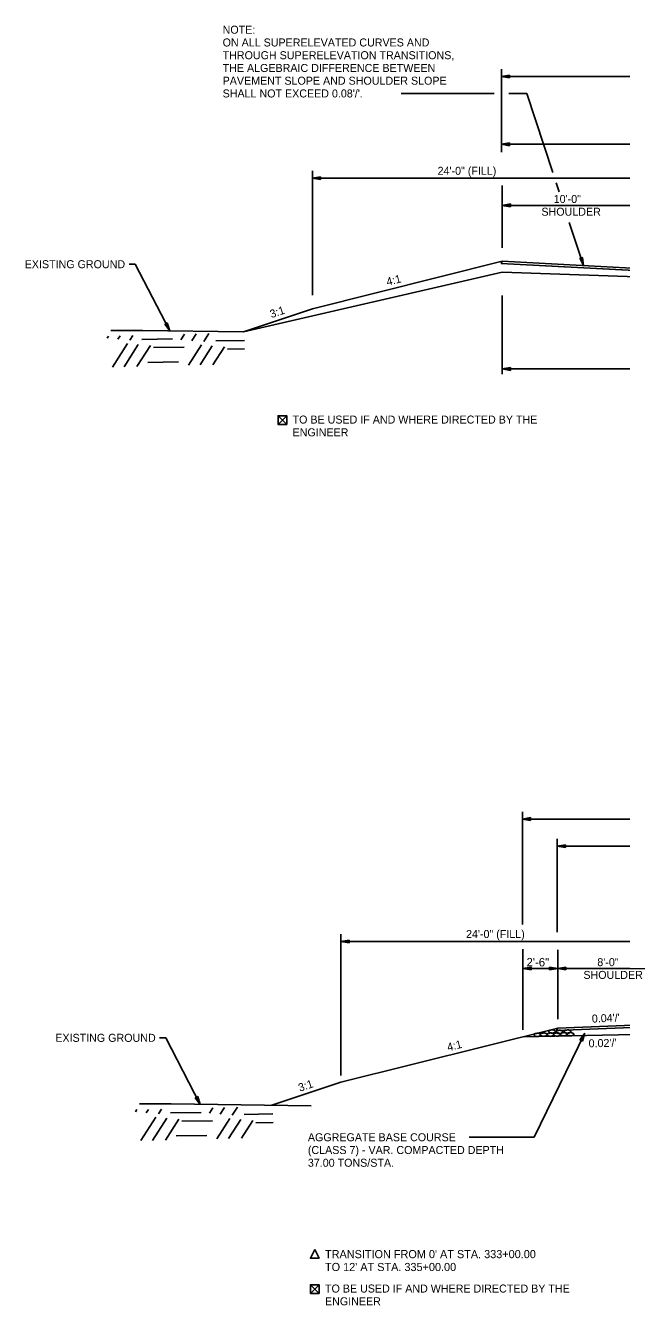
# Model space of a CAD drawing. Extents: x 1398183 to 1398373, y 1967240 to 1968889.
# Drawn here: x 1398185.9 to 1398229.8, y 1968484.8 to 1968579.2 of the extents above; entities that cross this region are included whole.
import ezdxf

# ---------------------------------------------------------------- set-up
doc = ezdxf.new("R2010")
doc.units = 0
for name, color, linetype in [('1', 7, 'Continuous'), ('10', 7, 'Continuous'), ('19', 7, 'Continuous'), ('42', 7, 'Continuous'), ('9', 7, 'Continuous')]:
    doc.layers.add(name, color=color, linetype=linetype)

# ---------------------------------------------------------------- blocks, each defined once
blk = doc.blocks.new('ROCKS')
at = {"layer": '1'}
blk.add_spline([(0.013, 0.06), (0.053, 0.053), (0.107, 0.033), (0.133, 0.013), (0.133, -0.007), (0.12, -0.033), (0.107, -0.04), (0.073, -0.053), (0.033, -0.067), (0.013, -0.067), (-0.02, -0.06), (-0.06, -0.053), (-0.087, -0.047), (-0.113, -0.02), (-0.113, -0.007), (-0.107, 0.02), (-0.087, 0.033), (-0.067, 0.047), (-0.033, 0.053), (-0.02, 0.06), (0.013, 0.06)], degree=3, dxfattribs=at)

msp = doc.modelspace()

# ---------------------------------------------------------------- linework, layer by layer
at = {"layer": '10'}
for p, q in [((1398204.509, 1968550.426), (1398205.15, 1968549.785)), ((1398205.15, 1968550.426), (1398204.509, 1968549.785)), ((1398204.89, 1968549.785), (1398204.901, 1968549.785)), ((1398206.903, 1968486.339), (1398207.544, 1968485.698)), ((1398207.544, 1968486.339), (1398206.903, 1968485.698)), ((1398207.284, 1968485.698), (1398207.296, 1968485.698))]:
    msp.add_line(p, q, dxfattribs=at)
for points in [[(1398204.901, 1968549.785), (1398205.15, 1968549.785), (1398205.15, 1968550.426), (1398204.509, 1968550.426), (1398204.509, 1968549.785), (1398204.89, 1968549.785)], [(1398207.296, 1968485.698), (1398207.544, 1968485.698), (1398207.544, 1968486.339), (1398206.903, 1968486.339), (1398206.903, 1968485.698), (1398207.284, 1968485.698)]]:
    msp.add_lwpolyline(points, dxfattribs=at)
msp.add_lwpolyline([(1398207.214, 1968488.933), (1398206.893, 1968488.292), (1398207.535, 1968488.292)], close=True, dxfattribs=at)
at = {"layer": '19'}
for p, q in [((1398220.994, 1968569.859), (1398220.994, 1968575.999)), ((1398221.594, 1968575.551), (1398220.994, 1968575.446)), ((1398272.994, 1968575.446), (1398220.994, 1968575.446)), ((1398220.994, 1968575.446), (1398221.594, 1968575.341)), ((1398221.594, 1968575.496), (1398221.154, 1968575.461)), ((1398221.154, 1968575.431), (1398221.594, 1968575.391)), ((1398221.594, 1968575.341), (1398221.594, 1968575.551)), ((1398220.466, 1968574.187), (1398213.602, 1968574.185)), ((1398222.858, 1968574.187), (1398221.532, 1968574.187)), ((1398222.858, 1968574.187), (1398224.78, 1968568.377)), ((1398221.594, 1968570.55), (1398220.994, 1968570.446)), ((1398220.994, 1968570.446), (1398282.96, 1968570.446)), ((1398220.994, 1968570.446), (1398221.594, 1968570.34)), ((1398221.594, 1968570.495), (1398221.154, 1968570.461)), ((1398221.154, 1968570.431), (1398221.594, 1968570.39)), ((1398221.594, 1968570.34), (1398221.594, 1968570.55)), ((1398207.052, 1968559.324), (1398207.052, 1968568.492)), ((1398207.652, 1968568.051), (1398207.052, 1968567.946)), ((1398231.052, 1968567.946), (1398207.052, 1968567.946)), ((1398207.052, 1968567.946), (1398207.652, 1968567.841)), ((1398207.652, 1968567.996), (1398207.212, 1968567.961)), ((1398207.212, 1968567.931), (1398207.652, 1968567.891)), ((1398207.652, 1968567.841), (1398207.652, 1968568.051)), ((1398221.052, 1968562.824), (1398221.052, 1968567.406)), ((1398225.032, 1968567.613), (1398225.251, 1968566.951)), ((1398221.652, 1968566.05), (1398221.052, 1968565.946)), ((1398221.052, 1968565.946), (1398221.652, 1968565.84)), ((1398221.052, 1968565.946), (1398231.052, 1968565.946)), ((1398221.652, 1968565.995), (1398221.212, 1968565.961)), ((1398221.652, 1968565.84), (1398221.652, 1968566.05)), ((1398221.212, 1968565.931), (1398221.652, 1968565.89)), ((1398226, 1968564.687), (1398227.052, 1968561.506)), ((1398221.052, 1968561.824), (1398207.052, 1968558.324)), ((1398221.052, 1968561.824), (1398220.967, 1968561.654)), ((1398226.972, 1968562.11), (1398226.773, 1968562.046)), ((1398226.773, 1968562.046), (1398227.052, 1968561.506)), ((1398226.818, 1968562.057), (1398226.989, 1968561.655)), ((1398227.014, 1968561.66), (1398226.922, 1968562.089)), ((1398227.052, 1968561.506), (1398226.972, 1968562.11)), ((1398221.052, 1968553.49), (1398221.052, 1968559.294)), ((1398207.052, 1968558.324), (1398201.951, 1968556.624)), ((1398196.144, 1968557.182), (1398196.33, 1968557.277)), ((1398196.514, 1968556.698), (1398196.144, 1968557.182)), ((1398196.431, 1968556.834), (1398196.194, 1968557.202)), ((1398196.29, 1968557.253), (1398196.453, 1968556.847)), ((1398196.33, 1968557.277), (1398196.514, 1968556.698)), ((1398221.652, 1968553.985), (1398221.052, 1968553.88)), ((1398221.052, 1968553.88), (1398221.652, 1968553.775)), ((1398221.052, 1968553.88), (1398255.052, 1968553.88)), ((1398221.652, 1968553.93), (1398221.212, 1968553.895)), ((1398221.212, 1968553.865), (1398221.652, 1968553.825)), ((1398221.652, 1968553.775), (1398221.652, 1968553.985)), ((1398222.545, 1968512.904), (1398222.545, 1968521.226)), ((1398223.145, 1968520.79), (1398222.545, 1968520.685)), ((1398222.545, 1968520.685), (1398279.917, 1968520.685)), ((1398222.545, 1968520.685), (1398223.145, 1968520.58)), ((1398223.145, 1968520.735), (1398222.705, 1968520.7)), ((1398222.705, 1968520.67), (1398223.145, 1968520.63)), ((1398223.145, 1968520.58), (1398223.145, 1968520.79)), ((1398225.119, 1968512.351), (1398225.119, 1968519.233)), ((1398225.719, 1968518.79), (1398225.119, 1968518.685)), ((1398225.719, 1968518.58), (1398225.719, 1968518.79)), ((1398275.152, 1968518.685), (1398225.119, 1968518.685)), ((1398225.119, 1968518.685), (1398225.719, 1968518.58)), ((1398225.719, 1968518.735), (1398225.279, 1968518.7)), ((1398225.279, 1968518.67), (1398225.719, 1968518.63)), ((1398209.15, 1968501.772), (1398209.15, 1968512.207)), ((1398209.75, 1968511.765), (1398209.15, 1968511.66)), ((1398233.15, 1968511.66), (1398209.15, 1968511.66)), ((1398209.15, 1968511.66), (1398209.75, 1968511.555)), ((1398209.75, 1968511.71), (1398209.31, 1968511.675)), ((1398209.31, 1968511.645), (1398209.75, 1968511.605)), ((1398209.75, 1968511.555), (1398209.75, 1968511.765)), ((1398222.578, 1968505.129), (1398222.578, 1968511.101)), ((1398225.15, 1968505.932), (1398225.15, 1968511.041)), ((1398223.178, 1968509.765), (1398222.578, 1968509.66)), ((1398222.578, 1968509.66), (1398225.15, 1968509.66)), ((1398222.578, 1968509.66), (1398223.178, 1968509.555)), ((1398223.178, 1968509.71), (1398222.738, 1968509.675)), ((1398222.738, 1968509.645), (1398223.178, 1968509.605)), ((1398223.178, 1968509.555), (1398223.178, 1968509.765)), ((1398224.55, 1968509.765), (1398224.55, 1968509.555)), ((1398225.15, 1968509.66), (1398224.55, 1968509.765)), ((1398224.99, 1968509.675), (1398224.55, 1968509.71)), ((1398224.55, 1968509.555), (1398225.15, 1968509.66)), ((1398224.55, 1968509.605), (1398224.99, 1968509.645)), ((1398225.75, 1968509.765), (1398225.15, 1968509.66)), ((1398225.15, 1968509.66), (1398225.75, 1968509.555)), ((1398225.15, 1968509.66), (1398233.15, 1968509.66)), ((1398225.75, 1968509.71), (1398225.31, 1968509.675)), ((1398225.31, 1968509.645), (1398225.75, 1968509.605)), ((1398225.75, 1968509.555), (1398225.75, 1968509.765)), ((1398225.15, 1968505.272), (1398209.15, 1968501.272)), ((1398223.415, 1968497.225), (1398227.143, 1968504.883)), ((1398225.15, 1968505.272), (1398225.065, 1968505.102)), ((1398227.143, 1968504.883), (1398226.779, 1968504.395)), ((1398227.061, 1968504.747), (1398226.828, 1968504.374)), ((1398226.922, 1968504.325), (1398227.086, 1968504.734)), ((1398226.966, 1968504.302), (1398227.143, 1968504.883)), ((1398226.779, 1968504.395), (1398226.966, 1968504.302)), ((1398209.15, 1968501.272), (1398204.049, 1968499.572)), ((1398198.401, 1968500.128), (1398198.587, 1968500.224)), ((1398198.771, 1968499.644), (1398198.401, 1968500.128)), ((1398198.689, 1968499.78), (1398198.451, 1968500.148)), ((1398198.548, 1968500.199), (1398198.71, 1968499.793)), ((1398198.587, 1968500.224), (1398198.771, 1968499.644)), ((1398218.617, 1968497.225), (1398223.415, 1968497.225))]:
    msp.add_line(p, q, dxfattribs=at)
for points in [[(1398193.514, 1968561.604), (1398193.96, 1968561.604), (1398196.514, 1968556.698)], [(1398220.967, 1968561.654), (1398243.052, 1968560.491), (1398267.137, 1968559.216), (1398273.137, 1968558.898)], [(1398221.052, 1968561.824), (1398231.052, 1968561.294), (1398243.052, 1968560.658), (1398255.052, 1968560.022), (1398267.052, 1968559.386), (1398273.052, 1968559.068)], [(1398225.065, 1968505.102), (1398233.065, 1968505.422), (1398245.15, 1968505.666), (1398269.237, 1968505.182), (1398275.235, 1968504.942)], [(1398245.15, 1968505.832), (1398233.15, 1968505.592), (1398225.15, 1968505.272)], [(1398233.15, 1968504.841), (1398222.578, 1968504.629)], [(1398195.772, 1968504.55), (1398196.218, 1968504.55), (1398198.771, 1968499.644)]]:
    msp.add_lwpolyline(points, dxfattribs=at)
for points in [[(1398220.967, 1968561.654), (1398230.818, 1968561.138), (1398243.052, 1968560.491), (1398267.137, 1968559.216), (1398273.137, 1968558.898), (1398273.052, 1968559.068), (1398267.052, 1968559.386), (1398243.052, 1968560.658), (1398231.052, 1968561.294), (1398221.052, 1968561.824)], [(1398225.065, 1968505.102), (1398233.065, 1968505.422), (1398245.15, 1968505.666), (1398269.252, 1968505.191), (1398275.237, 1968504.942), (1398275.15, 1968505.112), (1398269.152, 1968505.352), (1398245.15, 1968505.832), (1398233.15, 1968505.592), (1398225.15, 1968505.272)]]:
    msp.add_lwpolyline(points, close=True, dxfattribs=at)
at = {"layer": '42'}
msp.add_line((1398221.052, 1968561.011), (1398201.951, 1968556.624), dxfattribs=at)
for points in [[(1398221.052, 1968561.011), (1398243.052, 1968560.263), (1398255.052, 1968559.855)], [(1398192.182, 1968556.725), (1398194.519, 1968556.725), (1398201.951, 1968556.624)], [(1398194.28, 1968499.673), (1398196.617, 1968499.673), (1398206.951, 1968499.533)]]:
    msp.add_lwpolyline(points, dxfattribs=at)
at = {"layer": '9'}
for p, q in [((1398191.889, 1968556.15), (1398191.99, 1968556.306)), ((1398192.286, 1968554.019), (1398193.401, 1968555.759)), ((1398192.689, 1968556.076), (1398192.849, 1968556.327)), ((1398193.145, 1968554.039), (1398194.2, 1968555.686)), ((1398193.581, 1968556.005), (1398193.801, 1968556.35)), ((1398194.098, 1968554.062), (1398195.092, 1968555.614)), ((1398194.469, 1968556.063), (1398196.731, 1968556.099)), ((1398197.344, 1968556.039), (1398197.601, 1968556.44)), ((1398197.898, 1968554.152), (1398198.856, 1968555.648)), ((1398198.144, 1968555.965), (1398198.461, 1968556.461)), ((1398198.757, 1968554.173), (1398199.655, 1968555.574)), ((1398199.036, 1968555.894), (1398199.413, 1968556.483)), ((1398199.924, 1968555.952), (1398202.03, 1968555.985)), ((1398195.318, 1968555.453), (1398197.58, 1968555.488)), ((1398199.709, 1968554.195), (1398200.547, 1968555.503)), ((1398200.773, 1968555.341), (1398202.045, 1968555.361)), ((1398194.899, 1968554.367), (1398197.161, 1968554.402)), ((1398193.987, 1968499.098), (1398194.088, 1968499.255)), ((1398194.787, 1968499.025), (1398194.947, 1968499.275)), ((1398195.679, 1968498.953), (1398195.899, 1968499.298)), ((1398196.567, 1968499.011), (1398198.829, 1968499.047)), ((1398199.442, 1968498.987), (1398199.699, 1968499.388)), ((1398200.242, 1968498.913), (1398200.559, 1968499.409)), ((1398201.134, 1968498.842), (1398201.511, 1968499.432)), ((1398202.022, 1968498.9), (1398204.128, 1968498.933)), ((1398194.384, 1968496.967), (1398195.499, 1968498.708)), ((1398195.243, 1968496.987), (1398196.298, 1968498.634)), ((1398196.196, 1968497.01), (1398197.19, 1968498.562)), ((1398197.416, 1968498.401), (1398199.678, 1968498.436)), ((1398199.996, 1968497.1), (1398200.954, 1968498.596)), ((1398200.855, 1968497.121), (1398201.753, 1968498.523)), ((1398201.807, 1968497.144), (1398202.645, 1968498.451)), ((1398202.871, 1968498.29), (1398204.143, 1968498.309)), ((1398196.997, 1968497.315), (1398199.259, 1968497.35))]:
    msp.add_line(p, q, dxfattribs=at)

# ---------------------------------------------------------------- block references
at = {"layer": '1', "xscale": 1.968733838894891, "yscale": -1.968733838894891}
for p in [(1398223.626, 1968504.763), (1398224.104, 1968504.783), (1398224.602, 1968504.783), (1398224.715, 1968505.011), (1398225.075, 1968504.788), (1398225.266, 1968504.98), (1398225.574, 1968504.809), (1398225.859, 1968505.008), (1398226.072, 1968504.809)]:
    msp.add_blockref('ROCKS', p, dxfattribs=at)

# ---------------------------------------------------------------- texts
at = {"layer": '10'}
for s, height, p in [('24\'-0" (FILL)', 0.59001, (1398216.283, 1968568.197)), ('10\'-0"', 0.59, (1398224.851, 1968566.121)), ('SHOULDER', 0.59, (1398223.945, 1968565.181)), ('EXISTING GROUND', 0.59001, (1398185.816, 1968561.309)), ('24\'-0" (FILL)', 0.59001, (1398218.381, 1968511.912)), ('8\'-0"', 0.59, (1398228.07, 1968509.835)), ('SHOULDER', 0.59, (1398227.043, 1968508.895)), ('EXISTING GROUND', 0.59001, (1398188.074, 1968504.255))]:
    msp.add_text(s, height=height, dxfattribs=at).set_placement(p)
for s, height, rotation, p in [('4:1', 0.59, 14.03624, (1398212.584, 1968560.011)), ('3:1', 0.59, 18.43495, (1398204.02, 1968557.625)), ('TO BE USED IF AND WHERE DIRECTED BY THE ', 0.59001, 360, (1398205.582, 1968549.852)), ('ENGINEER', 0.59, 360, (1398205.582, 1968548.912)), ("0.04'/'", 0.59, 2.29061, (1398227.676, 1968505.669)), ('4:1', 0.59, 14.03624, (1398217.063, 1968503.555)), ('3:1', 0.59, 18.43495, (1398206.118, 1968500.573)), ('TO BE USED IF AND WHERE DIRECTED BY THE ', 0.59001, 360, (1398207.976, 1968485.765)), ('ENGINEER', 0.59, 360, (1398207.976, 1968484.825))]:
    msp.add_text(s, height=height, rotation=rotation, dxfattribs=at).set_placement(p)
at = {"layer": '19'}
for s, height, p in [('NOTE:', 0.59, (1398200.421, 1968578.603)), ('ON ALL SUPERELEVATED CURVES AND', 0.59001, (1398200.421, 1968577.663)), ('THROUGH SUPERELEVATION TRANSITIONS,', 0.59001, (1398200.421, 1968576.723)), ('THE ALGEBRAIC DIFFERENCE BETWEEN', 0.59001, (1398200.421, 1968575.783)), ('PAVEMENT SLOPE AND SHOULDER SLOPE', 0.59001, (1398200.421, 1968574.843)), ("SHALL NOT EXCEED 0.08'/'.", 0.59001, (1398200.421, 1968573.903)), ('2\'-6"', 0.625, (1398222.848, 1968509.818))]:
    msp.add_text(s, height=height, dxfattribs=at).set_placement(p)
for s, height, rotation, p in [("0.02'/'", 0.59, 1.14576, (1398227.433, 1968503.848)), ('AGGREGATE BASE COURSE', 0.59001, 360, (1398206.712, 1968496.922)), ('(CLASS 7) - VAR. COMPACTED DEPTH', 0.59001, 360, (1398206.712, 1968495.982)), ('37.00 TONS/STA.', 0.59001, 360, (1398206.712, 1968495.042))]:
    msp.add_text(s, height=height, rotation=rotation, dxfattribs=at).set_placement(p)
at = {"layer": '42'}
for s, p in [("TRANSITION FROM 0' AT STA. 333+00.00", (1398207.976, 1968488.3)), ("TO 12' AT STA. 335+00.00", (1398207.976, 1968487.35))]:
    msp.add_text(s, height=0.6, dxfattribs=at).set_placement(p)

doc.saveas('drawing.dxf')
